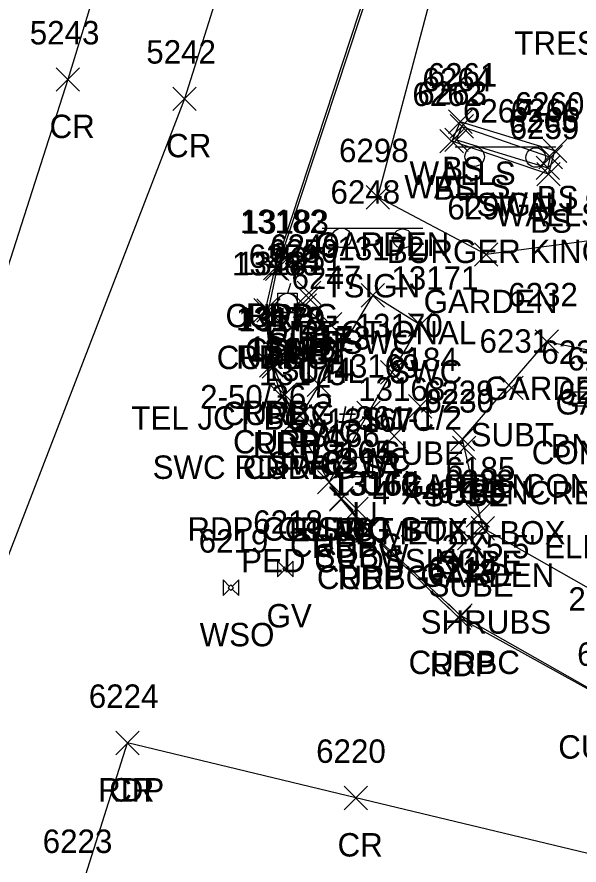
# Model space of a CAD drawing. Extents: x 1462089 to 1464015, y 730534 to 736144.
# Drawn here: x 1462544.3 to 1462592.3, y 731119.2 to 731191.6 of the extents above; entities that cross this region are included whole.
import ezdxf

# ---------------------------------------------------------------- set-up
doc = ezdxf.new("R2010")
doc.units = 0
for name, color, linetype in [('L_A', 7, 'Continuous'), ('L_C', 7, 'Continuous'), ('L_I', 7, 'Continuous'), ('L_TIC', 7, 'Continuous'), ('LAPB', 7, 'Continuous'), ('LELB', 7, 'Continuous'), ('LWS', 7, 'Continuous'), ('M_A', 7, 'Continuous'), ('M_C', 7, 'Continuous'), ('M_I', 7, 'Continuous'), ('MHBP', 7, 'Continuous'), ('P_A', 7, 'Continuous'), ('P_I', 7, 'Continuous'), ('P_TIC', 7, 'Continuous'), ('PET', 7, 'Continuous'), ('PRC', 7, 'Continuous'), ('R_A', 7, 'Continuous'), ('R_I', 7, 'Continuous'), ('R_TIC', 7, 'Continuous'), ('RC', 7, 'Continuous'), ('RSW', 7, 'Continuous'), ('S_A', 7, 'Continuous'), ('S_C', 7, 'Continuous'), ('S_I', 7, 'Continuous'), ('SSGN', 7, 'Continuous'), ('U_A', 7, 'Continuous'), ('U_C', 7, 'Continuous'), ('U_I', 7, 'Continuous'), ('U_TIC', 7, 'Continuous'), ('UDEFAULT', 7, 'Continuous'), ('ULP', 7, 'Continuous'), ('UP', 7, 'Continuous'), ('UWV', 7, 'Continuous')]:
    doc.layers.add(name, color=color, linetype=linetype)

msp = doc.modelspace()

# ---------------------------------------------------------------- linework, layer by layer
at = {"layer": 'L_TIC'}
for points in [[(1462581.162, 731181.703), (1462583.162, 731183.703)], [(1462583.162, 731181.703), (1462581.162, 731183.703)], [(1462581.284, 731181.303), (1462583.284, 731183.303)], [(1462583.284, 731181.303), (1462581.284, 731183.303)], [(1462580.425, 731180.038), (1462582.425, 731182.038)], [(1462582.425, 731180.038), (1462580.425, 731182.038)], [(1462580.425, 731180.038), (1462582.425, 731182.038)], [(1462582.425, 731180.038), (1462580.425, 731182.038)], [(1462580.837, 731180.144), (1462582.837, 731182.144)], [(1462582.837, 731180.144), (1462580.837, 731182.144)], [(1462580.837, 731180.144), (1462582.837, 731182.144)], [(1462582.837, 731180.144), (1462580.837, 731182.144)], [(1462589.248, 731179.221), (1462591.248, 731181.221)], [(1462591.248, 731179.221), (1462589.248, 731181.221)], [(1462588.879, 731178.666), (1462590.879, 731180.666)], [(1462590.879, 731178.666), (1462588.879, 731180.666)], [(1462588.879, 731178.666), (1462590.879, 731180.666)], [(1462590.879, 731178.666), (1462588.879, 731180.666)], [(1462588.648, 731177.769), (1462590.648, 731179.769)], [(1462590.648, 731177.769), (1462588.648, 731179.769)], [(1462588.695, 731177.217), (1462590.695, 731179.217)], [(1462590.695, 731177.217), (1462588.695, 731179.217)], [(1462588.695, 731177.217), (1462590.695, 731179.217)], [(1462590.695, 731177.217), (1462588.695, 731179.217)], [(1462574.109, 731175.245), (1462576.109, 731177.245)], [(1462576.109, 731175.245), (1462574.109, 731177.245)], [(1462583.36, 731170.351), (1462585.36, 731172.351)], [(1462585.36, 731170.351), (1462583.36, 731172.351)], [(1462588.558, 731162.933), (1462590.558, 731164.933)], [(1462590.558, 731162.933), (1462588.558, 731164.933)], [(1462581.361, 731154.597), (1462583.361, 731156.597)], [(1462583.361, 731154.597), (1462581.361, 731156.597)], [(1462583.08, 731146.979), (1462585.08, 731148.979)], [(1462585.08, 731146.979), (1462583.08, 731148.979)]]:
    msp.add_lwpolyline(points, dxfattribs=at)
at = {"layer": 'LAPB'}
for points in [[(1462598.962, 731197.414), (1462601.37, 731188.695), (1462600.501, 731184.167), (1462605.625, 731181.218), (1462604.985, 731174.079), (1462584.36, 731171.351), (1462575.109, 731176.245), (1462581.054, 731198.675), (1462586.856, 731202.661)], [(1462599.633, 731139.165), (1462584.08, 731147.979), (1462582.361, 731155.597), (1462589.558, 731163.933), (1462595.629, 731162.694), (1462600.875, 731157.274), (1462606.188, 731153.998)]]:
    msp.add_lwpolyline(points, dxfattribs=at)
at = {"layer": 'LELB'}
for points in [[(1462589.695, 731178.217), (1462590.248, 731180.221), (1462582.162, 731182.703), (1462581.425, 731181.038)], [(1462589.695, 731178.217), (1462581.425, 731181.038)]]:
    msp.add_lwpolyline(points, dxfattribs=at)
at = {"layer": 'LWS'}
for points in [[(1462581.837, 731181.144), (1462582.284, 731182.303), (1462589.879, 731179.666)], [(1462581.837, 731181.144), (1462589.648, 731178.769), (1462589.879, 731179.666)]]:
    msp.add_lwpolyline(points, dxfattribs=at)
at = {"layer": 'MHBP'}
msp.add_lwpolyline([(1462591.766, 731159.646), (1462593.016, 731159.646), (1462593.016, 731158.396), (1462591.766, 731158.396)], close=True, dxfattribs=at)
at = {"layer": 'P_TIC'}
for points in [[(1462547.642, 731185.301), (1462549.642, 731187.301)], [(1462549.642, 731185.301), (1462547.642, 731187.301)], [(1462557.596, 731183.663), (1462559.596, 731185.663)], [(1462559.596, 731183.663), (1462557.596, 731185.663)], [(1462565.352, 731169.188), (1462567.352, 731171.188)], [(1462567.352, 731169.188), (1462565.352, 731171.188)], [(1462564.522, 731165.597), (1462566.522, 731167.597)], [(1462566.522, 731165.597), (1462564.522, 731167.597)], [(1462565.018, 731160.878), (1462567.018, 731162.878)], [(1462567.018, 731160.878), (1462565.018, 731162.878)], [(1462565.956, 731158.2), (1462567.956, 731160.2)], [(1462567.956, 731158.2), (1462565.956, 731160.2)], [(1462566.995, 731156.199), (1462568.995, 731158.199)], [(1462568.995, 731156.199), (1462566.995, 731158.199)], [(1462569.963, 731150.921), (1462571.963, 731152.921)], [(1462571.963, 731150.921), (1462569.963, 731152.921)], [(1462570.982, 731149.454), (1462572.982, 731151.454)], [(1462572.982, 731149.454), (1462570.982, 731151.454)], [(1462573.202, 731146.763), (1462575.202, 731148.763)], [(1462575.202, 731146.763), (1462573.202, 731148.763)], [(1462581.051, 731139.338), (1462583.051, 731141.338)], [(1462583.051, 731139.338), (1462581.051, 731141.338)], [(1462552.734, 731128.646), (1462554.734, 731130.646)], [(1462554.734, 731128.646), (1462552.734, 731130.646)], [(1462552.734, 731128.646), (1462554.734, 731130.646)], [(1462554.734, 731128.646), (1462552.734, 731130.646)], [(1462572.242, 731123.95), (1462574.242, 731125.95)], [(1462574.242, 731123.95), (1462572.242, 731125.95)]]:
    msp.add_lwpolyline(points, dxfattribs=at)
at = {"layer": 'PET'}
for points in [[(1462566.352, 731170.188), (1462581.47, 731216.162)], [(1462574.202, 731147.763), (1462571.982, 731150.454), (1462570.963, 731151.921), (1462567.995, 731157.199), (1462566.956, 731159.2), (1462566.018, 731161.878), (1462565.522, 731166.597), (1462566.352, 731170.188)], [(1462574.202, 731147.763), (1462582.051, 731140.338)], [(1462617.993, 731127.43), (1462594.885, 731133.233), (1462582.051, 731140.338)], [(1462373.445, 730550.573), (1462388.309, 730598.891), (1462401.963, 730641.783), (1462433.168, 730744.632), (1462438.196, 730760.147), (1462452.976, 730810.554), (1462463.625, 730846.159), (1462471.864, 730873.588), (1462478.576, 730896.599), (1462485.477, 730919.066), (1462495.517, 730952.686), (1462508.095, 730994.119), (1462517.419, 731025.054), (1462526.796, 731054.959), (1462537.856, 731087.551), (1462549.797, 731117.253), (1462553.734, 731129.646)]]:
    msp.add_lwpolyline(points, dxfattribs=at)
at = {"layer": 'PRC'}
for points in [[(1462782.015, 731950.466), (1462768.89, 731909.836), (1462760.031, 731877.27), (1462749.824, 731847.721), (1462735.793, 731799.645), (1462732.293, 731789.156), (1462718.713, 731743.615), (1462707.108, 731705.526), (1462694.32, 731660.71), (1462680.69, 731618.482), (1462665.703, 731575.678), (1462653.408, 731528.208), (1462637.717, 731478.421), (1462624.246, 731431.842), (1462612.569, 731394.542), (1462600.922, 731353.761), (1462584.46, 731303.134), (1462565.785, 731242.263), (1462548.642, 731186.301), (1462531.515, 731132.984), (1462517.28, 731085.282)], [(1462793.023, 731947.647), (1462779.179, 731905.946), (1462772.135, 731874.551), (1462759.588, 731843.402), (1462745.797, 731796.521), (1462742.091, 731785.853), (1462729.199, 731739.315), (1462722.155, 731715.561), (1462711.035, 731679.919), (1462704.897, 731658.033), (1462690.283, 731612.577), (1462677.1, 731571.216), (1462663.072, 731525.56), (1462648.796, 731477.498), (1462634.522, 731430.676), (1462623.138, 731390.715), (1462610.921, 731351.233), (1462594.7, 731298.487), (1462575.733, 731238.978), (1462558.596, 731184.663), (1462539.605, 731135.536), (1462521.539, 731083.728), (1462509.353, 731045.029)], [(1462612.649, 731115.515), (1462573.242, 731124.95), (1462553.734, 731129.646)]]:
    msp.add_lwpolyline(points, dxfattribs=at)
at = {"layer": 'R_TIC'}
for points in [[(1462565.516, 731169.141), (1462567.516, 731171.141)], [(1462567.516, 731169.141), (1462565.516, 731171.141)], [(1462573.69, 731166.875), (1462575.69, 731168.875)], [(1462575.69, 731166.875), (1462573.69, 731168.875)], [(1462564.772, 731165.571), (1462566.772, 731167.571)], [(1462566.772, 731165.571), (1462564.772, 731167.571)], [(1462577.732, 731164.35), (1462579.732, 731166.35)], [(1462579.732, 731164.35), (1462577.732, 731166.35)], [(1462565.223, 731160.789), (1462567.223, 731162.789)], [(1462567.223, 731160.789), (1462565.223, 731162.789)], [(1462575.333, 731160.299), (1462577.333, 731162.299)], [(1462577.333, 731160.299), (1462575.333, 731162.299)], [(1462569.092, 731159.243), (1462571.092, 731161.243)], [(1462571.092, 731159.243), (1462569.092, 731161.243)], [(1462566.167, 731158.37), (1462568.167, 731160.37)], [(1462568.167, 731158.37), (1462566.167, 731160.37)], [(1462573.323, 731156.842), (1462575.323, 731158.842)], [(1462575.323, 731156.842), (1462573.323, 731158.842)], [(1462566.995, 731156.199), (1462568.995, 731158.199)], [(1462568.995, 731156.199), (1462566.995, 731158.199)], [(1462566.995, 731156.199), (1462568.995, 731158.199)], [(1462568.995, 731156.199), (1462566.995, 731158.199)], [(1462567.469, 731156.55), (1462569.469, 731158.55)], [(1462569.469, 731156.55), (1462567.469, 731158.55)], [(1462569.963, 731150.921), (1462571.963, 731152.921)], [(1462571.963, 731150.921), (1462569.963, 731152.921)], [(1462569.963, 731150.921), (1462571.963, 731152.921)], [(1462571.963, 731150.921), (1462569.963, 731152.921)], [(1462571.023, 731149.538), (1462573.023, 731151.538)], [(1462573.023, 731149.538), (1462571.023, 731151.538)], [(1462573.328, 731146.792), (1462575.328, 731148.792)], [(1462575.328, 731146.792), (1462573.328, 731148.792)], [(1462581.164, 731139.533), (1462583.164, 731141.533)], [(1462583.164, 731139.533), (1462581.164, 731141.533)]]:
    msp.add_lwpolyline(points, dxfattribs=at)
at = {"layer": 'RC'}
for points in [[(1462566.516, 731170.141), (1462581.732, 731216.184)], [(1462567.995, 731157.199), (1462567.167, 731159.37), (1462566.223, 731161.789), (1462565.772, 731166.571), (1462566.516, 731170.141)], [(1462574.328, 731147.792), (1462572.023, 731150.538), (1462570.963, 731151.921)], [(1462574.328, 731147.792), (1462582.164, 731140.533)], [(1462618.159, 731127.464), (1462594.945, 731133.308), (1462582.164, 731140.533)]]:
    msp.add_lwpolyline(points, dxfattribs=at)
at = {"layer": 'RSW'}
msp.add_lwpolyline([(1462570.963, 731151.921), (1462574.323, 731157.842), (1462576.333, 731161.299), (1462578.732, 731165.35), (1462574.69, 731167.875), (1462570.092, 731160.243), (1462568.469, 731157.55), (1462567.995, 731157.199)], dxfattribs=at)
at = {"layer": 'SSGN'}
for p, q in [((1462581.726, 731180.55), (1462590.323, 731180.55)), ((1462585.748, 731179.647), (1462585.748, 731179.647)), ((1462570.362, 731173.616), (1462578.96, 731173.616)), ((1462574.385, 731172.712), (1462574.385, 731172.712))]:
    msp.add_line(p, q, dxfattribs=at)
for centre in [(1462583.388, 731179.717), (1462588.602, 731179.647), (1462572.024, 731172.783), (1462577.238, 731172.712)]:
    msp.add_circle(centre, 0.833, dxfattribs=at)
at = {"layer": 'U_TIC'}
for points in [[(1462568.233, 731167.081), (1462570.233, 731169.081)], [(1462570.233, 731167.081), (1462568.233, 731169.081)], [(1462568.184, 731166.654), (1462570.184, 731168.654)], [(1462570.184, 731166.654), (1462568.184, 731168.654)], [(1462567.888, 731165.993), (1462569.888, 731167.993)], [(1462569.888, 731165.993), (1462567.888, 731167.993)], [(1462585.543, 731158.972), (1462587.543, 731160.972)], [(1462587.543, 731158.972), (1462585.543, 731160.972)], [(1462577.732, 731157.398), (1462579.732, 731159.398)], [(1462579.732, 731157.398), (1462577.732, 731159.398)], [(1462581.486, 731153.861), (1462583.486, 731155.861)], [(1462583.486, 731153.861), (1462581.486, 731155.861)], [(1462572.298, 731148.643), (1462574.298, 731150.643)], [(1462574.298, 731148.643), (1462572.298, 731150.643)], [(1462582.65, 731148.065), (1462584.65, 731150.065)], [(1462584.65, 731148.065), (1462582.65, 731150.065)], [(1462581.911, 731146.143), (1462583.911, 731148.143)], [(1462583.911, 731146.143), (1462581.911, 731148.143)]]:
    msp.add_lwpolyline(points, dxfattribs=at)
at = {"layer": 'UDEFAULT'}
for points in [[(1462570.051, 731164.401), (1462572.051, 731166.401)], [(1462572.051, 731164.401), (1462570.051, 731166.401)], [(1462575.505, 731154.864), (1462577.505, 731156.864)], [(1462577.505, 731154.864), (1462575.505, 731156.864)], [(1462581.361, 731154.597), (1462583.361, 731156.597)], [(1462583.361, 731154.597), (1462581.361, 731156.597)]]:
    msp.add_lwpolyline(points, dxfattribs=at)
at = {"layer": 'ULP'}
for p, q in [((1462573.997, 731154.884), (1462573.83, 731154.05)), ((1462572.997, 731152.384), (1462572.997, 731154.05)), ((1462572.997, 731154.05), (1462574.663, 731154.05)), ((1462574.663, 731154.05), (1462574.663, 731152.384)), ((1462573.83, 731153.217), (1462573.83, 731153.217)), ((1462574.663, 731152.384), (1462572.997, 731152.384)), ((1462573.58, 731151.55), (1462573.83, 731152.384))]:
    msp.add_line(p, q, dxfattribs=at)
at = {"layer": 'UP'}
for p, q in [((1462567.647, 731168.884), (1462567.397, 731168.051)), ((1462566.564, 731166.384), (1462566.564, 731168.051)), ((1462566.564, 731168.051), (1462568.23, 731168.051)), ((1462568.23, 731168.051), (1462568.23, 731166.384)), ((1462567.397, 731167.217), (1462567.397, 731167.217)), ((1462568.23, 731166.384), (1462566.564, 731166.384)), ((1462567.147, 731165.551), (1462567.397, 731166.384))]:
    msp.add_line(p, q, dxfattribs=at)
msp.add_circle((1462567.397, 731167.217), 0.833, dxfattribs=at)
at = {"layer": 'UWV'}
for p, q in [((1462566.542, 731145.179), (1462567.875, 731143.846)), ((1462567.875, 731145.179), (1462566.542, 731143.846)), ((1462561.895, 731143.568), (1462562.444, 731143.02)), ((1462563.229, 731143.568), (1462562.68, 731143.02)), ((1462562.444, 731142.784), (1462561.895, 731142.235)), ((1462562.68, 731142.784), (1462563.229, 731142.235))]:
    msp.add_line(p, q, dxfattribs=at)
for points in [[(1462566.542, 731145.179), (1462566.542, 731143.846)], [(1462567.875, 731143.846), (1462567.875, 731145.179)], [(1462561.895, 731143.568), (1462561.895, 731142.235)], [(1462563.229, 731142.235), (1462563.229, 731143.568)]]:
    msp.add_lwpolyline(points, dxfattribs=at)
msp.add_lwpolyline([(1462562.798, 731142.902), (1462562.562, 731143.138), (1462562.326, 731142.902), (1462562.562, 731142.666)], close=True, dxfattribs=at)
msp.add_circle((1462567.209, 731144.512), 0.167, dxfattribs=at)

# ---------------------------------------------------------------- texts
at = {"layer": 'L_A'}
for s, p in [('BS', (1462580.603, 731177.703)), ('WALLS', (1462577.827, 731177.303)), ('WALLS', (1462577.38, 731176.144)), ('WALLS', (1462577.38, 731176.144)), ('BS', (1462579.866, 731176.038)), ('BS', (1462579.866, 731176.038)), ('BS', (1462588.689, 731175.221)), ('WALLS', (1462585.423, 731174.666)), ('WALLS', (1462585.423, 731174.666)), ('WALLS', (1462585.191, 731173.769)), ('BS', (1462588.136, 731173.217)), ('BS', (1462588.136, 731173.217)), ('GARDEN', (1462569.779, 731171.245)), ('GARDEN', (1462579.029, 731166.351)), ('GARDEN', (1462584.227, 731158.933)), ('GARDEN', (1462590.298, 731157.694)), ('CONCPAD', (1462588.266, 731153.454)), ('GARDEN', (1462577.03, 731150.597)), ('CONCPAD', (1462587.501, 731150.604)), ('GARDEN', (1462578.749, 731142.979))]:
    msp.add_text(s, height=2, dxfattribs=at).set_placement(p)
at = {"layer": 'L_C'}
for s, p in [('TRES & SHRUBS', (1462586.773, 731188.414)), ('TRES & SHRUBS', (1462586.773, 731188.414)), ('SHRUBS', (1462578.773, 731138.979))]:
    msp.add_text(s, height=2, dxfattribs=at).set_placement(p)
at = {"layer": 'L_I'}
for s, p in [('6261', (1462579.375, 731185.703)), ('6264', (1462578.929, 731185.303)), ('6263', (1462578.482, 731184.144)), ('6263', (1462578.482, 731184.144)), ('6262', (1462578.07, 731184.038)), ('6262', (1462578.07, 731184.038)), ('6266', (1462586.47, 731182.666)), ('6266', (1462586.47, 731182.666)), ('6260', (1462586.808, 731183.221)), ('6265', (1462586.293, 731181.769)), ('6259', (1462586.38, 731181.217)), ('6259', (1462586.38, 731181.217)), ('6298', (1462571.802, 731179.245)), ('6297', (1462581.053, 731174.351)), ('6232', (1462586.251, 731166.933)), ('6237', (1462591.314, 731161.454)), ('6229', (1462579.046, 731158.597)), ('6238', (1462590.548, 731158.604)), ('6228', (1462580.773, 731150.979))]:
    msp.add_text(s, height=2, dxfattribs=at).set_placement(p)
at = {"layer": 'M_A'}
msp.add_text('BND', height=2, dxfattribs=at).set_placement((1462589.88, 731154.021))
at = {"layer": 'M_C'}
msp.add_text('4"X4" CONCRETE -FLUSH', height=2, dxfattribs=at).set_placement((1462574.659, 731150.021))
at = {"layer": 'M_I'}
msp.add_text('6234', height=2, dxfattribs=at).set_placement((1462589.084, 731162.021))
at = {"layer": 'P_A'}
for s, p in [('CR', (1462547.075, 731181.301)), ('CR', (1462557.029, 731179.663)), ('RDP', (1462563.84, 731165.188)), ('RDP', (1462563.011, 731161.597)), ('RDP', (1462563.506, 731156.878)), ('RDP', (1462564.445, 731154.2)), ('RDP', (1462565.483, 731152.199)), ('RDP', (1462568.451, 731146.921)), ('RDP', (1462569.47, 731145.454)), ('RDP', (1462571.691, 731142.763)), ('RDP', (1462579.54, 731135.338)), ('RDP', (1462551.222, 731124.646)), ('CR', (1462552.167, 731124.646)), ('CR', (1462571.675, 731119.95))]:
    msp.add_text(s, height=2, dxfattribs=at).set_placement(p)
at = {"layer": 'P_I'}
for s, p in [('5243', (1462545.383, 731189.301)), ('5242', (1462555.336, 731187.663)), ('13182', (1462563.329, 731173.188)), ('13181', (1462563.066, 731169.597)), ('13178', (1462562.995, 731164.878)), ('13177', (1462563.933, 731162.2)), ('13175', (1462564.971, 731160.199)), ('13166', (1462567.837, 731154.921)), ('13165', (1462568.911, 731153.454)), ('13162', (1462571.132, 731150.763)), ('6213', (1462579.311, 731143.338)), ('6212', (1462592.145, 731136.233)), ('6224', (1462550.427, 731132.646)), ('6224', (1462550.427, 731132.646)), ('6220', (1462569.848, 731127.95)), ('6223', (1462546.49, 731120.253))]:
    msp.add_text(s, height=2, dxfattribs=at).set_placement(p)
at = {"layer": 'R_A'}
for s, p in [('CURBG', (1462562.099, 731165.141)), ('SWC', (1462572.052, 731162.875)), ('CURBG', (1462561.355, 731161.571)), ('SWC', (1462576.094, 731160.35)), ('CURBG', (1462561.806, 731156.789)), ('SWC', (1462573.695, 731156.299)), ('SWC', (1462567.454, 731155.243)), ('CURBG', (1462562.749, 731154.37)), ('SWC', (1462565.831, 731152.55)), ('SWC', (1462571.685, 731152.842)), ('SWC RDP CG ST', (1462555.876, 731152.199)), ('CURBG', (1462563.577, 731152.199)), ('RDP CG SWC ST', (1462558.845, 731146.921)), ('CURBG', (1462566.546, 731146.921)), ('CURBG', (1462567.605, 731145.538)), ('CURBG', (1462569.911, 731142.792)), ('CURBC', (1462577.747, 731135.533)), ('CURBC', (1462590.528, 731128.308))]:
    msp.add_text(s, height=2, dxfattribs=at).set_placement(p)
at = {"layer": 'R_I'}
for s, p in [('13183', (1462563.493, 731173.141)), ('13172', (1462571.667, 731170.875)), ('13180', (1462562.662, 731169.571)), ('13171', (1462576.276, 731168.35)), ('13179', (1462563.192, 731164.789)), ('13170', (1462573.223, 731164.299)), ('13173', (1462567.069, 731163.243)), ('13176', (1462564.088, 731162.37)), ('13175', (1462564.971, 731160.199)), ('13175', (1462564.971, 731160.199)), ('13174', (1462565.446, 731160.55)), ('13169', (1462571.244, 731160.842)), ('13166', (1462567.837, 731154.921)), ('13166', (1462567.837, 731154.921)), ('13164', (1462568.952, 731153.538)), ('13163', (1462571.257, 731150.792)), ('6214', (1462579.424, 731143.533))]:
    msp.add_text(s, height=2, dxfattribs=at).set_placement(p)
at = {"layer": 'S_A'}
for p in [(1462581.924, 731174.629), (1462570.56, 731167.695)]:
    msp.add_text('TSIGN', height=2, dxfattribs=at).set_placement(p)
at = {"layer": 'S_C'}
for s, p in [('BURGER KING!', (1462575.885, 731170.629)), ('DIRECTIONAL', (1462565.545, 731163.695))]:
    msp.add_text(s, height=2, dxfattribs=at).set_placement(p)
at = {"layer": 'S_I'}
for s, p in [('6267', (1462582.389, 731182.629)), ('6248', (1462571.072, 731175.695))]:
    msp.add_text(s, height=2, dxfattribs=at).set_placement(p)
at = {"layer": 'U_A'}
for s, p in [('SUBT', (1462565.68, 731162.654)), ('SUBE', (1462565.769, 731163.081)), ('COMB', (1462563.783, 731162.217)), ('SUBT', (1462565.384, 731161.993)), ('UTIL', (1462568.217, 731160.401)), ('SUBT', (1462583.039, 731154.972)), ('SUBE', (1462575.267, 731153.398)), ('UTIL', (1462573.67, 731150.864)), ('UTIL', (1462579.526, 731150.597)), ('SUBE', (1462579.021, 731149.861)), ('LI', (1462572.932, 731148.217)), ('SUBW', (1462569.707, 731144.643)), ('SUBE', (1462580.186, 731144.065)), ('SUBE', (1462579.447, 731142.143)), ('GV', (1462565.61, 731139.512)), ('WSO', (1462559.893, 731137.902))]:
    msp.add_text(s, height=2, dxfattribs=at).set_placement(p)
at = {"layer": 'U_C'}
for s, p in [('2-50/36.5', (1462559.933, 731158.217)), ('TEL JCT BOX #361-1/2', (1462554.059, 731156.401)), ('EL JCT BOX', (1462567.544, 731146.864)), ('EL METER BOX', (1462571.385, 731146.597)), ("2'X5.5' ELEC JCT BOX", (1462580.565, 731145.415)), ('PED CROSSING', (1462563.444, 731144.217)), ("2'X5.5' ELEC JCT BOX", (1462591.397, 731140.944))]:
    msp.add_text(s, height=2, dxfattribs=at).set_placement(p)
at = {"layer": 'U_I'}
for s, p in [('6249', (1462565.918, 731171.081)), ('6250', (1462565.79, 731170.654)), ('6252', (1462564.09, 731170.217)), ('6251', (1462566.148, 731169.993)), ('6247', (1462567.744, 731168.401)), ('6231', (1462583.803, 731162.972)), ('6184', (1462575.992, 731161.398)), ('13168', (1462573.434, 731158.864)), ('6229', (1462579.046, 731158.597)), ('6230', (1462579.092, 731157.861)), ('13167', (1462570.759, 731156.217)), ('6217', (1462570.558, 731152.643)), ('6185', (1462580.91, 731152.065)), ('6186', (1462580.116, 731150.143)), ('6218', (1462564.469, 731147.512)), ('6219', (1462559.814, 731145.902))]:
    msp.add_text(s, height=2, dxfattribs=at).set_placement(p)

doc.saveas('drawing.dxf')
